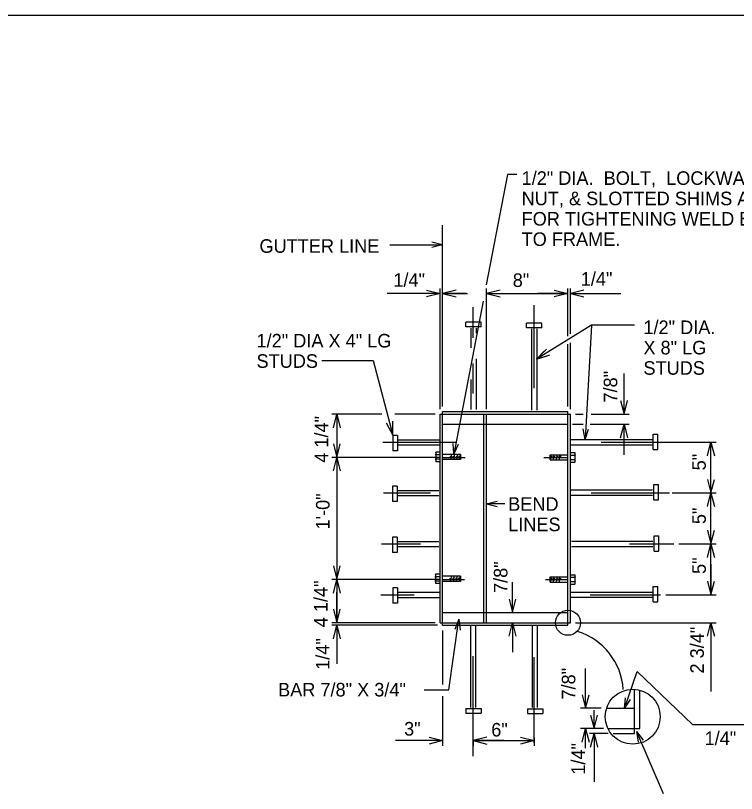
# Model space of a CAD drawing. Extents: x 973.2 to 1069.7, y 1484.4 to 1549.5.
# Drawn here: x 1034.82 to 1052.53, y 1525.25 to 1544.36 of the extents above; entities that cross this region are included whole.
import ezdxf

# ---------------------------------------------------------------- set-up
doc = ezdxf.new("R2010")
doc.units = 0
doc.layers.add('Level 1', color=7, linetype='Continuous')
doc.layers.add('Level 2', color=7, linetype='Continuous')

msp = doc.modelspace()

# ---------------------------------------------------------------- linework, layer by layer
at = {"layer": 'Level 1'}
msp.add_line((1065.368, 1544.364), (981.8, 1544.364), dxfattribs=at)
at = {"layer": 'Level 2'}
for p, q in [((1046.904, 1540.457), (1046.385, 1537.745)), ((1047.137, 1540.457), (1046.904, 1540.457)), ((1045.312, 1534.759), (1045.312, 1539.217)), ((1044.016, 1538.73), (1045.104, 1538.73)), ((1045.304, 1538.73), (1045.044, 1538.795)), ((1045.304, 1538.73), (1045.044, 1538.665)), ((1045.104, 1538.73), (1045.304, 1538.73)), ((1045.25, 1534.696), (1045.25, 1537.659)), ((1046.391, 1534.696), (1046.391, 1537.659)), ((1048.391, 1536.487), (1048.391, 1537.659)), ((1048.453, 1536.545), (1048.453, 1537.659)), ((1045.25, 1537.534), (1043.947, 1537.534)), ((1045.899, 1537.534), (1045.312, 1537.534)), ((1045.312, 1537.534), (1045.921, 1537.534)), ((1046.391, 1537.534), (1048.391, 1537.534)), ((1048.391, 1537.534), (1047.641, 1537.534)), ((1048.453, 1537.534), (1049.688, 1537.534)), ((1046.309, 1537.347), (1045.59, 1533.586)), ((1046.063, 1536.449), (1046.063, 1537.2)), ((1047.563, 1535.211), (1047.563, 1537.249)), ((1046.256, 1536.828), (1045.88, 1536.828)), ((1045.88, 1536.714), (1045.88, 1536.828)), ((1046.256, 1536.714), (1046.256, 1536.828)), ((1047.747, 1536.808), (1047.371, 1536.808)), ((1047.371, 1536.694), (1047.371, 1536.808)), ((1047.747, 1536.694), (1047.747, 1536.808)), ((1046.256, 1536.714), (1045.88, 1536.714)), ((1046.017, 1536.201), (1046.017, 1536.686)), ((1046.142, 1536.564), (1046.142, 1536.686)), ((1047.747, 1536.694), (1047.371, 1536.694)), ((1047.508, 1534.666), (1047.508, 1536.666)), ((1048.968, 1536.755), (1047.623, 1535.924)), ((1047.633, 1534.666), (1047.633, 1536.666)), ((1048.968, 1536.755), (1048.816, 1533.949)), ((1050.028, 1536.755), (1048.968, 1536.755)), ((1048.391, 1534.759), (1048.391, 1536.287)), ((1048.453, 1534.696), (1048.453, 1536.325)), ((1047.623, 1535.924), (1047.81, 1536.116)), ((1042.344, 1535.886), (1043.607, 1535.886)), ((1043.607, 1535.886), (1044.092, 1534.054)), ((1046.142, 1534.686), (1046.142, 1535.934)), ((1047.623, 1535.924), (1047.878, 1536.006)), ((1046.063, 1535.076), (1046.063, 1535.819)), ((1049.771, 1534.571), (1049.771, 1535.568)), ((1046.017, 1534.686), (1046.017, 1535.419)), ((1043.815, 1534.571), (1042.588, 1534.571)), ((1042.712, 1534.571), (1042.712, 1533.509)), ((1045.125, 1534.571), (1044.14, 1534.571)), ((1045.25, 1534.571), (1048.453, 1534.571)), ((1045.25, 1529.446), (1045.25, 1534.571)), ((1045.312, 1529.384), (1045.312, 1534.634)), ((1045.312, 1534.634), (1048.391, 1534.634)), ((1046.328, 1529.446), (1046.328, 1534.571)), ((1046.391, 1529.446), (1046.391, 1534.571)), ((1048.391, 1529.384), (1048.391, 1534.634)), ((1048.453, 1529.446), (1048.453, 1534.571)), ((1048.578, 1534.571), (1048.768, 1534.571)), ((1048.959, 1534.571), (1049.896, 1534.571)), ((1045.312, 1534.321), (1048.391, 1534.321)), ((1048.501, 1534.321), (1048.768, 1534.321)), ((1048.94, 1534.321), (1049.896, 1534.321)), ((1049.771, 1533.571), (1049.771, 1534.321)), ((1048.816, 1533.949), (1048.765, 1534.212)), ((1048.816, 1533.949), (1048.895, 1534.205)), ((1044.088, 1534.049), (1044.088, 1533.673)), ((1044.202, 1534.049), (1044.088, 1534.049)), ((1044.202, 1534.049), (1044.202, 1533.673)), ((1045.229, 1533.935), (1044.229, 1533.935)), ((1048.459, 1533.945), (1050.459, 1533.945)), ((1050.487, 1533.706), (1050.487, 1534.082)), ((1050.487, 1534.082), (1050.601, 1534.082)), ((1050.601, 1533.706), (1050.601, 1534.082)), ((1043.839, 1533.884), (1045.659, 1533.884)), ((1045.229, 1533.81), (1044.229, 1533.81)), ((1045.59, 1533.586), (1045.575, 1533.854)), ((1045.59, 1533.586), (1045.703, 1533.83)), ((1048.459, 1533.82), (1050.459, 1533.82)), ((1049.205, 1533.884), (1050.964, 1533.884)), ((1050.934, 1533.884), (1052.03, 1533.884)), ((1051.905, 1532.634), (1051.905, 1533.884)), ((1044.202, 1533.673), (1044.088, 1533.673)), ((1045.147, 1533.574), (1045.141, 1533.585)), ((1045.142, 1533.628), (1045.146, 1533.638)), ((1045.142, 1533.628), (1045.142, 1533.417)), ((1045.253, 1533.574), (1045.142, 1533.574)), ((1045.143, 1533.563), (1045.147, 1533.574)), ((1045.253, 1533.638), (1045.146, 1533.638)), ((1045.755, 1533.583), (1045.317, 1533.583)), ((1045.526, 1533.571), (1045.515, 1533.467)), ((1045.566, 1533.542), (1045.56, 1533.488)), ((1045.595, 1533.574), (1045.584, 1533.47)), ((1045.643, 1533.541), (1045.637, 1533.488)), ((1045.672, 1533.573), (1045.661, 1533.469)), ((1045.711, 1533.544), (1045.706, 1533.49)), ((1045.74, 1533.576), (1045.729, 1533.472)), ((1045.755, 1533.583), (1045.755, 1533.458)), ((1047.953, 1533.446), (1047.953, 1533.571)), ((1047.953, 1533.571), (1048.391, 1533.571)), ((1047.968, 1533.454), (1047.979, 1533.558)), ((1048.036, 1533.456), (1048.047, 1533.56)), ((1048.065, 1533.488), (1048.071, 1533.541)), ((1048.113, 1533.456), (1048.124, 1533.56)), ((1048.142, 1533.488), (1048.148, 1533.541)), ((1048.182, 1533.458), (1048.193, 1533.562)), ((1048.211, 1533.49), (1048.216, 1533.543)), ((1048.455, 1533.626), (1048.561, 1533.626)), ((1048.455, 1533.564), (1048.566, 1533.564)), ((1048.567, 1533.579), (1048.56, 1533.565)), ((1048.56, 1533.565), (1048.565, 1533.551)), ((1048.566, 1533.612), (1048.561, 1533.626)), ((1048.567, 1533.578), (1048.562, 1533.563)), ((1048.562, 1533.563), (1048.565, 1533.55)), ((1048.567, 1533.58), (1048.564, 1533.566)), ((1048.564, 1533.566), (1048.567, 1533.554)), ((1048.566, 1533.401), (1048.566, 1533.612)), ((1050.487, 1533.706), (1050.601, 1533.706)), ((1045.259, 1533.509), (1042.588, 1533.509)), ((1042.712, 1533.509), (1042.712, 1530.509)), ((1045.144, 1533.463), (1045.141, 1533.475)), ((1045.141, 1533.452), (1045.146, 1533.467)), ((1045.141, 1533.45), (1045.148, 1533.464)), ((1045.141, 1533.449), (1045.144, 1533.463)), ((1045.253, 1533.465), (1045.142, 1533.465)), ((1045.142, 1533.417), (1045.147, 1533.403)), ((1045.146, 1533.467), (1045.143, 1533.479)), ((1045.148, 1533.464), (1045.143, 1533.478)), ((1045.253, 1533.403), (1045.147, 1533.403)), ((1045.312, 1533.509), (1045.867, 1533.509)), ((1045.755, 1533.458), (1045.317, 1533.458)), ((1045.497, 1533.539), (1045.492, 1533.486)), ((1047.801, 1533.509), (1048.391, 1533.509)), ((1047.953, 1533.446), (1048.391, 1533.446)), ((1047.997, 1533.486), (1048.002, 1533.539)), ((1048.455, 1533.456), (1048.566, 1533.456)), ((1048.455, 1533.391), (1048.562, 1533.391)), ((1048.565, 1533.466), (1048.561, 1533.455)), ((1048.561, 1533.455), (1048.567, 1533.444)), ((1048.566, 1533.401), (1048.562, 1533.391)), ((1044.081, 1532.8), (1044.081, 1532.424)), ((1044.195, 1532.8), (1044.081, 1532.8)), ((1044.195, 1532.8), (1044.195, 1532.424)), ((1050.5, 1532.47), (1050.5, 1532.846)), ((1050.5, 1532.846), (1050.614, 1532.846)), ((1050.614, 1532.47), (1050.614, 1532.846)), ((1043.856, 1532.634), (1045.014, 1532.634)), ((1045.223, 1532.686), (1044.223, 1532.686)), ((1048.473, 1532.709), (1050.473, 1532.709)), ((1048.963, 1532.634), (1050.884, 1532.634)), ((1050.95, 1532.634), (1052.03, 1532.634)), ((1051.905, 1531.384), (1051.905, 1532.634)), ((1044.195, 1532.424), (1044.081, 1532.424)), ((1045.223, 1532.561), (1044.223, 1532.561)), ((1046.389, 1532.365), (1046.649, 1532.43)), ((1048.473, 1532.584), (1050.473, 1532.584)), ((1050.5, 1532.47), (1050.614, 1532.47)), ((1046.837, 1532.365), (1046.389, 1532.365)), ((1046.389, 1532.365), (1046.649, 1532.3)), ((1044.081, 1531.55), (1044.081, 1531.174)), ((1044.195, 1531.55), (1044.081, 1531.55)), ((1044.195, 1531.55), (1044.195, 1531.174)), ((1048.479, 1531.447), (1050.479, 1531.447)), ((1050.507, 1531.208), (1050.507, 1531.584)), ((1050.507, 1531.584), (1050.621, 1531.584)), ((1050.621, 1531.208), (1050.621, 1531.584)), ((1043.807, 1531.384), (1044.772, 1531.384)), ((1045.215, 1531.436), (1044.223, 1531.436)), ((1045.223, 1531.311), (1044.223, 1531.311)), ((1048.479, 1531.322), (1050.479, 1531.322)), ((1049.903, 1531.384), (1050.991, 1531.384)), ((1051.116, 1531.384), (1052.03, 1531.384)), ((1051.905, 1530.134), (1051.905, 1531.384)), ((1044.195, 1531.174), (1044.081, 1531.174)), ((1050.507, 1531.208), (1050.621, 1531.208)), ((1051.905, 1530.884), (1051.905, 1530.134)), ((1045.247, 1530.509), (1042.588, 1530.509)), ((1042.712, 1530.509), (1042.712, 1529.446)), ((1045.141, 1530.579), (1045.134, 1530.589)), ((1045.136, 1530.632), (1045.139, 1530.642)), ((1045.136, 1530.632), (1045.136, 1530.422)), ((1045.136, 1530.567), (1045.141, 1530.579)), ((1045.247, 1530.578), (1045.136, 1530.578)), ((1045.139, 1530.471), (1045.136, 1530.484)), ((1045.247, 1530.642), (1045.139, 1530.642)), ((1045.748, 1530.588), (1045.311, 1530.588)), ((1045.312, 1530.509), (1045.853, 1530.509)), ((1045.491, 1530.544), (1045.485, 1530.49)), ((1045.52, 1530.576), (1045.509, 1530.472)), ((1045.559, 1530.546), (1045.554, 1530.493)), ((1045.588, 1530.578), (1045.577, 1530.474)), ((1045.636, 1530.546), (1045.631, 1530.492)), ((1045.665, 1530.578), (1045.654, 1530.474)), ((1045.705, 1530.548), (1045.699, 1530.495)), ((1045.734, 1530.58), (1045.723, 1530.476)), ((1045.748, 1530.588), (1045.748, 1530.463)), ((1047.841, 1530.509), (1048.391, 1530.509)), ((1047.953, 1530.446), (1047.953, 1530.571)), ((1047.953, 1530.571), (1048.391, 1530.571)), ((1047.968, 1530.454), (1047.979, 1530.558)), ((1047.997, 1530.486), (1048.002, 1530.539)), ((1048.036, 1530.456), (1048.047, 1530.56)), ((1048.065, 1530.488), (1048.071, 1530.541)), ((1048.113, 1530.456), (1048.124, 1530.56)), ((1048.142, 1530.488), (1048.148, 1530.541)), ((1048.182, 1530.458), (1048.193, 1530.562)), ((1048.211, 1530.49), (1048.216, 1530.543)), ((1048.455, 1530.626), (1048.561, 1530.626)), ((1048.455, 1530.564), (1048.566, 1530.564)), ((1048.567, 1530.579), (1048.56, 1530.565)), ((1048.56, 1530.565), (1048.565, 1530.551)), ((1048.566, 1530.612), (1048.561, 1530.626)), ((1048.567, 1530.578), (1048.562, 1530.563)), ((1048.562, 1530.563), (1048.565, 1530.55)), ((1048.567, 1530.58), (1048.564, 1530.566)), ((1048.564, 1530.566), (1048.567, 1530.554)), ((1048.566, 1530.401), (1048.566, 1530.612)), ((1044.088, 1530.301), (1044.088, 1529.925)), ((1044.202, 1530.301), (1044.088, 1530.301)), ((1044.202, 1530.301), (1044.202, 1529.925)), ((1045.137, 1530.467), (1045.135, 1530.48)), ((1045.135, 1530.456), (1045.139, 1530.471)), ((1045.135, 1530.455), (1045.141, 1530.469)), ((1045.135, 1530.454), (1045.137, 1530.467)), ((1045.141, 1530.469), (1045.136, 1530.482)), ((1045.247, 1530.47), (1045.136, 1530.47)), ((1045.136, 1530.422), (1045.141, 1530.408)), ((1045.247, 1530.408), (1045.141, 1530.408)), ((1045.748, 1530.463), (1045.311, 1530.463)), ((1047.03, 1529.696), (1047.03, 1530.446)), ((1047.953, 1530.446), (1048.391, 1530.446)), ((1048.455, 1530.456), (1048.566, 1530.456)), ((1048.455, 1530.391), (1048.562, 1530.391)), ((1048.565, 1530.466), (1048.561, 1530.455)), ((1048.561, 1530.455), (1048.567, 1530.444)), ((1048.566, 1530.401), (1048.562, 1530.391)), ((1050.487, 1529.958), (1050.487, 1530.334)), ((1050.487, 1530.334), (1050.601, 1530.334)), ((1050.601, 1529.958), (1050.601, 1530.334)), ((1042.712, 1529.446), (1042.712, 1530.196)), ((1043.79, 1530.134), (1044.611, 1530.134)), ((1045.229, 1530.187), (1044.229, 1530.187)), ((1048.459, 1530.197), (1050.459, 1530.197)), ((1048.936, 1530.134), (1050.669, 1530.134)), ((1050.794, 1530.134), (1052.03, 1530.134)), ((1044.202, 1529.925), (1044.088, 1529.925)), ((1045.229, 1530.062), (1044.229, 1530.062)), ((1048.459, 1530.072), (1050.459, 1530.072)), ((1050.487, 1529.958), (1050.601, 1529.958)), ((1045.312, 1529.696), (1048.391, 1529.696)), ((1045.467, 1527.794), (1045.714, 1529.531)), ((1045.714, 1529.531), (1045.613, 1529.283)), ((1045.714, 1529.531), (1045.742, 1529.264)), ((1047.057, 1529.696), (1047.155, 1529.696)), ((1045.125, 1529.446), (1042.588, 1529.446)), ((1045.188, 1529.384), (1042.588, 1529.384)), ((1042.712, 1529.384), (1042.712, 1528.439)), ((1045.25, 1529.446), (1048.453, 1529.446)), ((1045.312, 1529.384), (1048.391, 1529.384)), ((1045.994, 1529.367), (1045.994, 1527.367)), ((1046.119, 1529.367), (1046.119, 1527.367)), ((1047.03, 1529.446), (1047.03, 1528.723)), ((1047.122, 1529.446), (1047.155, 1529.446)), ((1047.512, 1529.361), (1047.512, 1527.361)), ((1047.637, 1529.361), (1047.637, 1527.361)), ((1048.578, 1529.446), (1052.03, 1529.446)), ((1051.905, 1529.446), (1051.905, 1527.757)), ((1045.312, 1529.259), (1045.312, 1527.928)), ((1046.063, 1526.17), (1046.063, 1528.629)), ((1047.563, 1526.493), (1047.563, 1528.602)), ((1048.825, 1527.346), (1048.825, 1528.322)), ((1049.782, 1527.338), (1050.093, 1528.246)), ((1050.093, 1528.246), (1051.451, 1526.946)), ((1044.855, 1527.794), (1045.467, 1527.794)), ((1045.312, 1527.641), (1045.312, 1526.425)), ((1050.03, 1526.721), (1050.03, 1527.792)), ((1050.155, 1526.846), (1050.155, 1527.792)), ((1049.782, 1527.338), (1049.805, 1527.605)), ((1049.782, 1527.338), (1049.928, 1527.563)), ((1045.88, 1527.34), (1046.256, 1527.34)), ((1045.88, 1527.34), (1045.88, 1527.226)), ((1046.256, 1527.34), (1046.256, 1527.226)), ((1047.398, 1527.333), (1047.774, 1527.333)), ((1047.398, 1527.333), (1047.398, 1527.219)), ((1047.774, 1527.333), (1047.774, 1527.219)), ((1049.208, 1527.346), (1048.7, 1527.346)), ((1049.032, 1526.846), (1049.032, 1527.296)), ((1049.333, 1527.346), (1050.03, 1527.346)), ((1045.88, 1527.226), (1046.256, 1527.226)), ((1047.398, 1527.219), (1047.774, 1527.219)), ((1051.451, 1526.946), (1053.881, 1526.946)), ((1049.265, 1526.846), (1048.7, 1526.846)), ((1048.825, 1526.363), (1048.825, 1526.846)), ((1049.379, 1526.721), (1048.921, 1526.721)), ((1049.032, 1526.721), (1049.032, 1525.538)), ((1049.39, 1526.846), (1050.155, 1526.846)), ((1049.504, 1526.721), (1050.03, 1526.721)), ((1050.077, 1526.774), (1050.731, 1525.252)), ((1050.077, 1526.774), (1050.239, 1526.561)), ((1050.077, 1526.774), (1050.12, 1526.509)), ((1045.312, 1526.55), (1044.158, 1526.55)), ((1046.813, 1526.55), (1046.063, 1526.55)), ((1046.063, 1526.55), (1047.563, 1526.55)), ((1046.063, 1526.529), (1046.063, 1526.425)), ((1047.563, 1526.621), (1047.563, 1526.425))]:
    msp.add_line(p, q, dxfattribs=at)
for points in [[(1044.917, 1537.617), (1045.25, 1537.534), (1044.917, 1537.451)], [(1045.646, 1537.617), (1045.312, 1537.534), (1045.646, 1537.451)], [(1046.724, 1537.617), (1046.391, 1537.534), (1046.724, 1537.451)], [(1048.057, 1537.617), (1048.391, 1537.534), (1048.057, 1537.451)], [(1048.786, 1537.617), (1048.453, 1537.534), (1048.786, 1537.451)], [(1047.863, 1536.17), (1047.623, 1535.924), (1047.95, 1536.028)], [(1049.687, 1534.904), (1049.771, 1534.571), (1049.854, 1534.904)], [(1042.629, 1534.238), (1042.712, 1534.571), (1042.796, 1534.238)], [(1043.927, 1534.357), (1044.091, 1534.055), (1044.089, 1534.398)], [(1049.687, 1533.988), (1049.771, 1534.321), (1049.854, 1533.988)], [(1042.629, 1533.842), (1042.712, 1533.509), (1042.796, 1533.842)], [(1051.822, 1533.55), (1051.905, 1533.884), (1051.989, 1533.55)], [(1042.629, 1533.175), (1042.712, 1533.509), (1042.796, 1533.175)], [(1051.822, 1532.967), (1051.905, 1532.634), (1051.989, 1532.967)], [(1051.822, 1532.3), (1051.905, 1532.634), (1051.989, 1532.3)], [(1051.822, 1531.717), (1051.905, 1531.384), (1051.989, 1531.717)], [(1051.822, 1531.05), (1051.905, 1531.384), (1051.989, 1531.05)], [(1042.629, 1530.842), (1042.712, 1530.509), (1042.796, 1530.842)], [(1042.629, 1530.175), (1042.712, 1530.509), (1042.796, 1530.175)], [(1051.822, 1530.467), (1051.905, 1530.134), (1051.989, 1530.467)], [(1046.946, 1530.029), (1047.03, 1529.696), (1047.113, 1530.029)], [(1042.629, 1529.779), (1042.712, 1529.446), (1042.796, 1529.779)], [(1042.629, 1529.05), (1042.712, 1529.384), (1042.796, 1529.05)], [(1046.946, 1529.113), (1047.03, 1529.446), (1047.113, 1529.113)], [(1051.822, 1529.113), (1051.905, 1529.446), (1051.989, 1529.113)], [(1048.742, 1527.679), (1048.825, 1527.346), (1048.909, 1527.679)], [(1048.948, 1527.179), (1049.032, 1526.846), (1049.115, 1527.179)], [(1048.742, 1526.513), (1048.825, 1526.846), (1048.909, 1526.513)], [(1048.948, 1526.388), (1049.032, 1526.721), (1049.115, 1526.388)], [(1044.979, 1526.633), (1045.312, 1526.55), (1044.979, 1526.466)], [(1046.396, 1526.633), (1046.063, 1526.55), (1046.396, 1526.466)], [(1047.229, 1526.633), (1047.563, 1526.55), (1047.229, 1526.466)]]:
    msp.add_lwpolyline(points, dxfattribs=at)
for centre, radius in [((1048.392, 1529.445), 0.308), ((1049.983, 1527.138), 0.675)]:
    msp.add_circle(centre, radius, dxfattribs=at)
msp.add_arc((1048.167, 1527.711), 1.585, 3.3693, 73.0621, dxfattribs=at)

# ---------------------------------------------------------------- texts
for s, height, p in [('1/2" DIA.  BOLT,  LOCKWASHER,  ', 0.33333, (1047.253, 1540.204)), ("NUT, & SLOTTED SHIMS AS REQ'D.", 0.33333, (1047.253, 1539.704)), ('FOR TIGHTENING WELD BOLT HEAD ', 0.33333, (1047.253, 1539.204)), ('TO FRAME.', 0.3333, (1047.253, 1538.704)), ('GUTTER LINE', 0.33333, (1040.811, 1538.535)), (' 1/4"', 0.3333, (1043.978, 1537.701)), (' 8"', 0.3333, (1046.911, 1537.696)), (' 1/4"', 0.3333, (1048.583, 1537.728)), ('1/2" DIA. ', 0.3333, (1050.246, 1536.539)), ('1/2" DIA X 4" LG', 0.33333, (1040.739, 1536.209)), ('X 8" LG', 0.3333, (1050.246, 1536.039)), ('STUDS ', 0.3333, (1040.739, 1535.709)), ('STUDS ', 0.3333, (1050.246, 1535.539)), ('BEND ', 0.3333, (1046.923, 1532.196)), ('LINES', 0.3333, (1046.923, 1531.696)), ('BAR 7/8" X 3/4"', 0.33333, (1041.269, 1527.635)), (' 3"', 0.3333, (1044.242, 1526.675)), (' 6"', 0.3333, (1046.383, 1526.651)), ('1/4"', 0.3333, (1051.75, 1526.441))]:
    msp.add_text(s, height=height, dxfattribs=at).set_placement(p)
for s, p in [('7/8"', (1049.604, 1534.856)), (' 4 1/4"', (1042.501, 1533.253)), ('5"', (1051.78, 1533.189)), ('1\'-0"', (1042.534, 1531.737)), ('5"', (1051.78, 1531.869)), ('7/8"', (1046.905, 1530.177)), ('7/8"', (1046.905, 1530.177)), ('5"', (1051.78, 1530.645)), (' 4 1/4"', (1042.485, 1529.211)), ('2 3/4"', (1051.731, 1528.199)), (' 1/4"', (1042.532, 1528.165)), ('7/8"', (1048.573, 1527.559)), ('1/4"', (1048.811, 1525.713))]:
    msp.add_text(s, height=0.3333, rotation=90, dxfattribs=at).set_placement(p)

doc.saveas('drawing.dxf')
